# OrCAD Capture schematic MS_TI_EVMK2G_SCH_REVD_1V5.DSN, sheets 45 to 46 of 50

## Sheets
45 44. BOARD MANAGEMENT CONTROL_1: size C; title: BOARD MANAGEMENT CONTROL_1
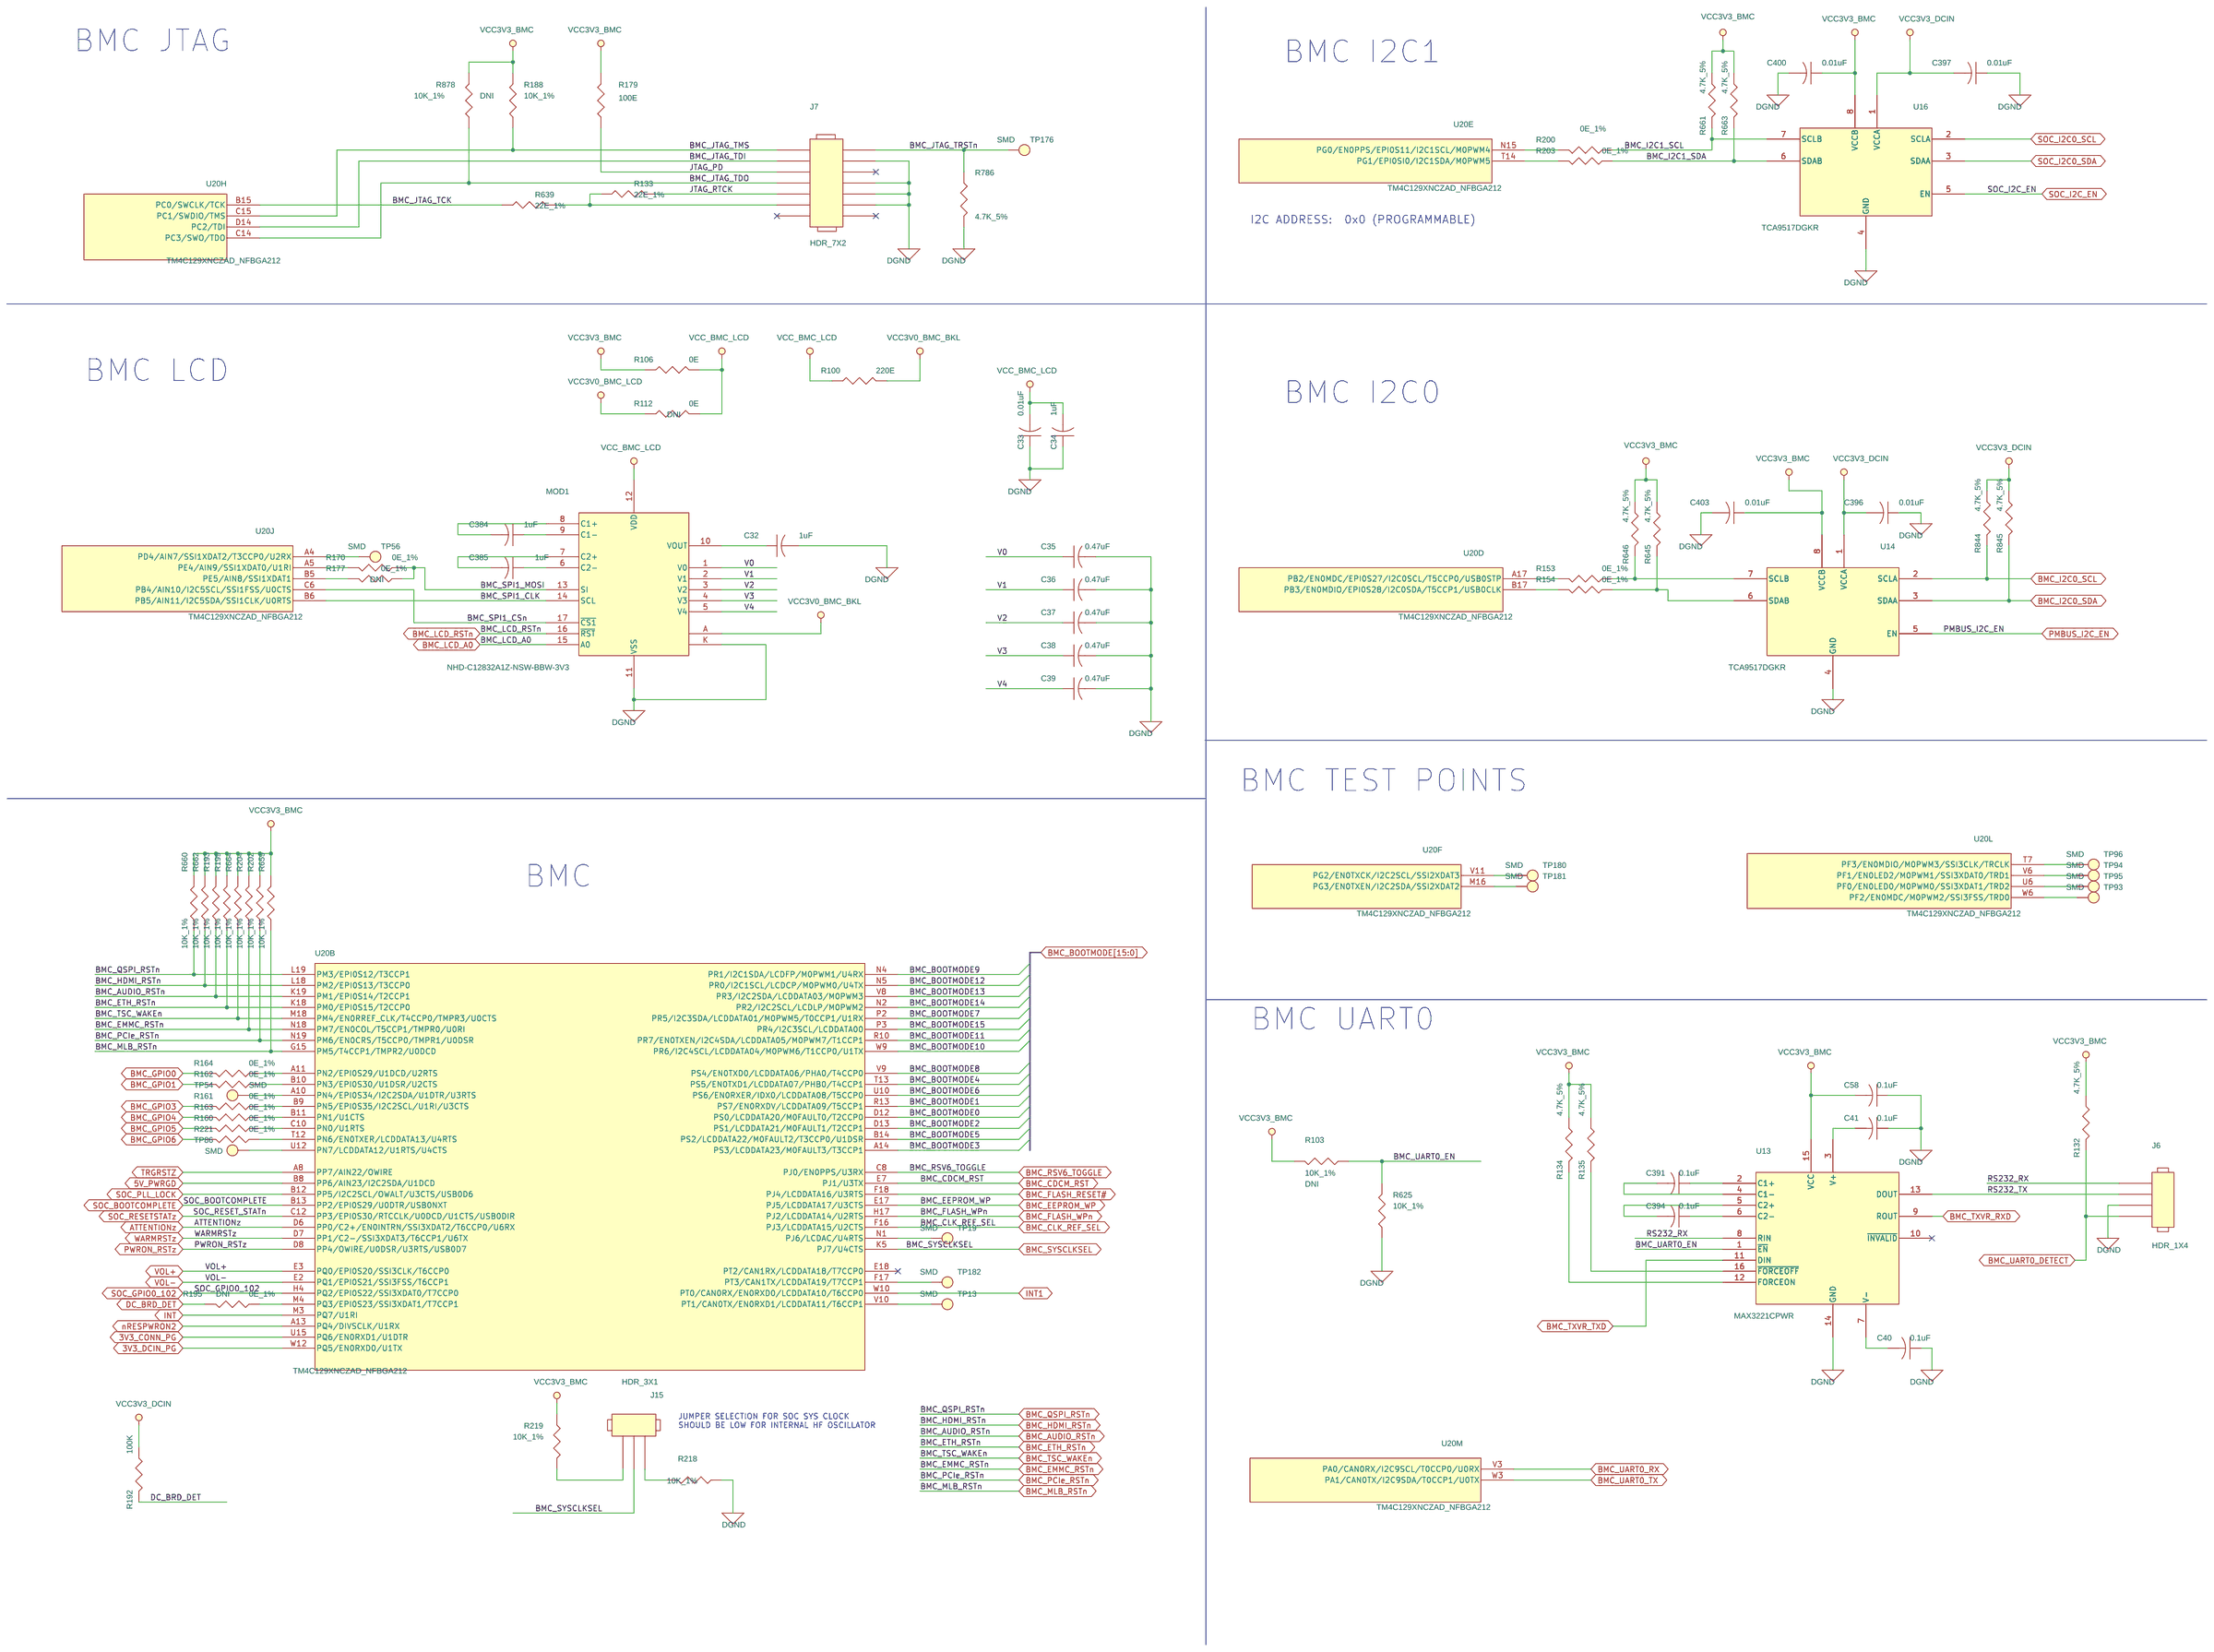
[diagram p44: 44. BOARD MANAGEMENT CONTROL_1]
46 45. BOARD MANAGEMENT CONTROL_2: size C; title: BOARD MANAGEMENT CONTROL_2
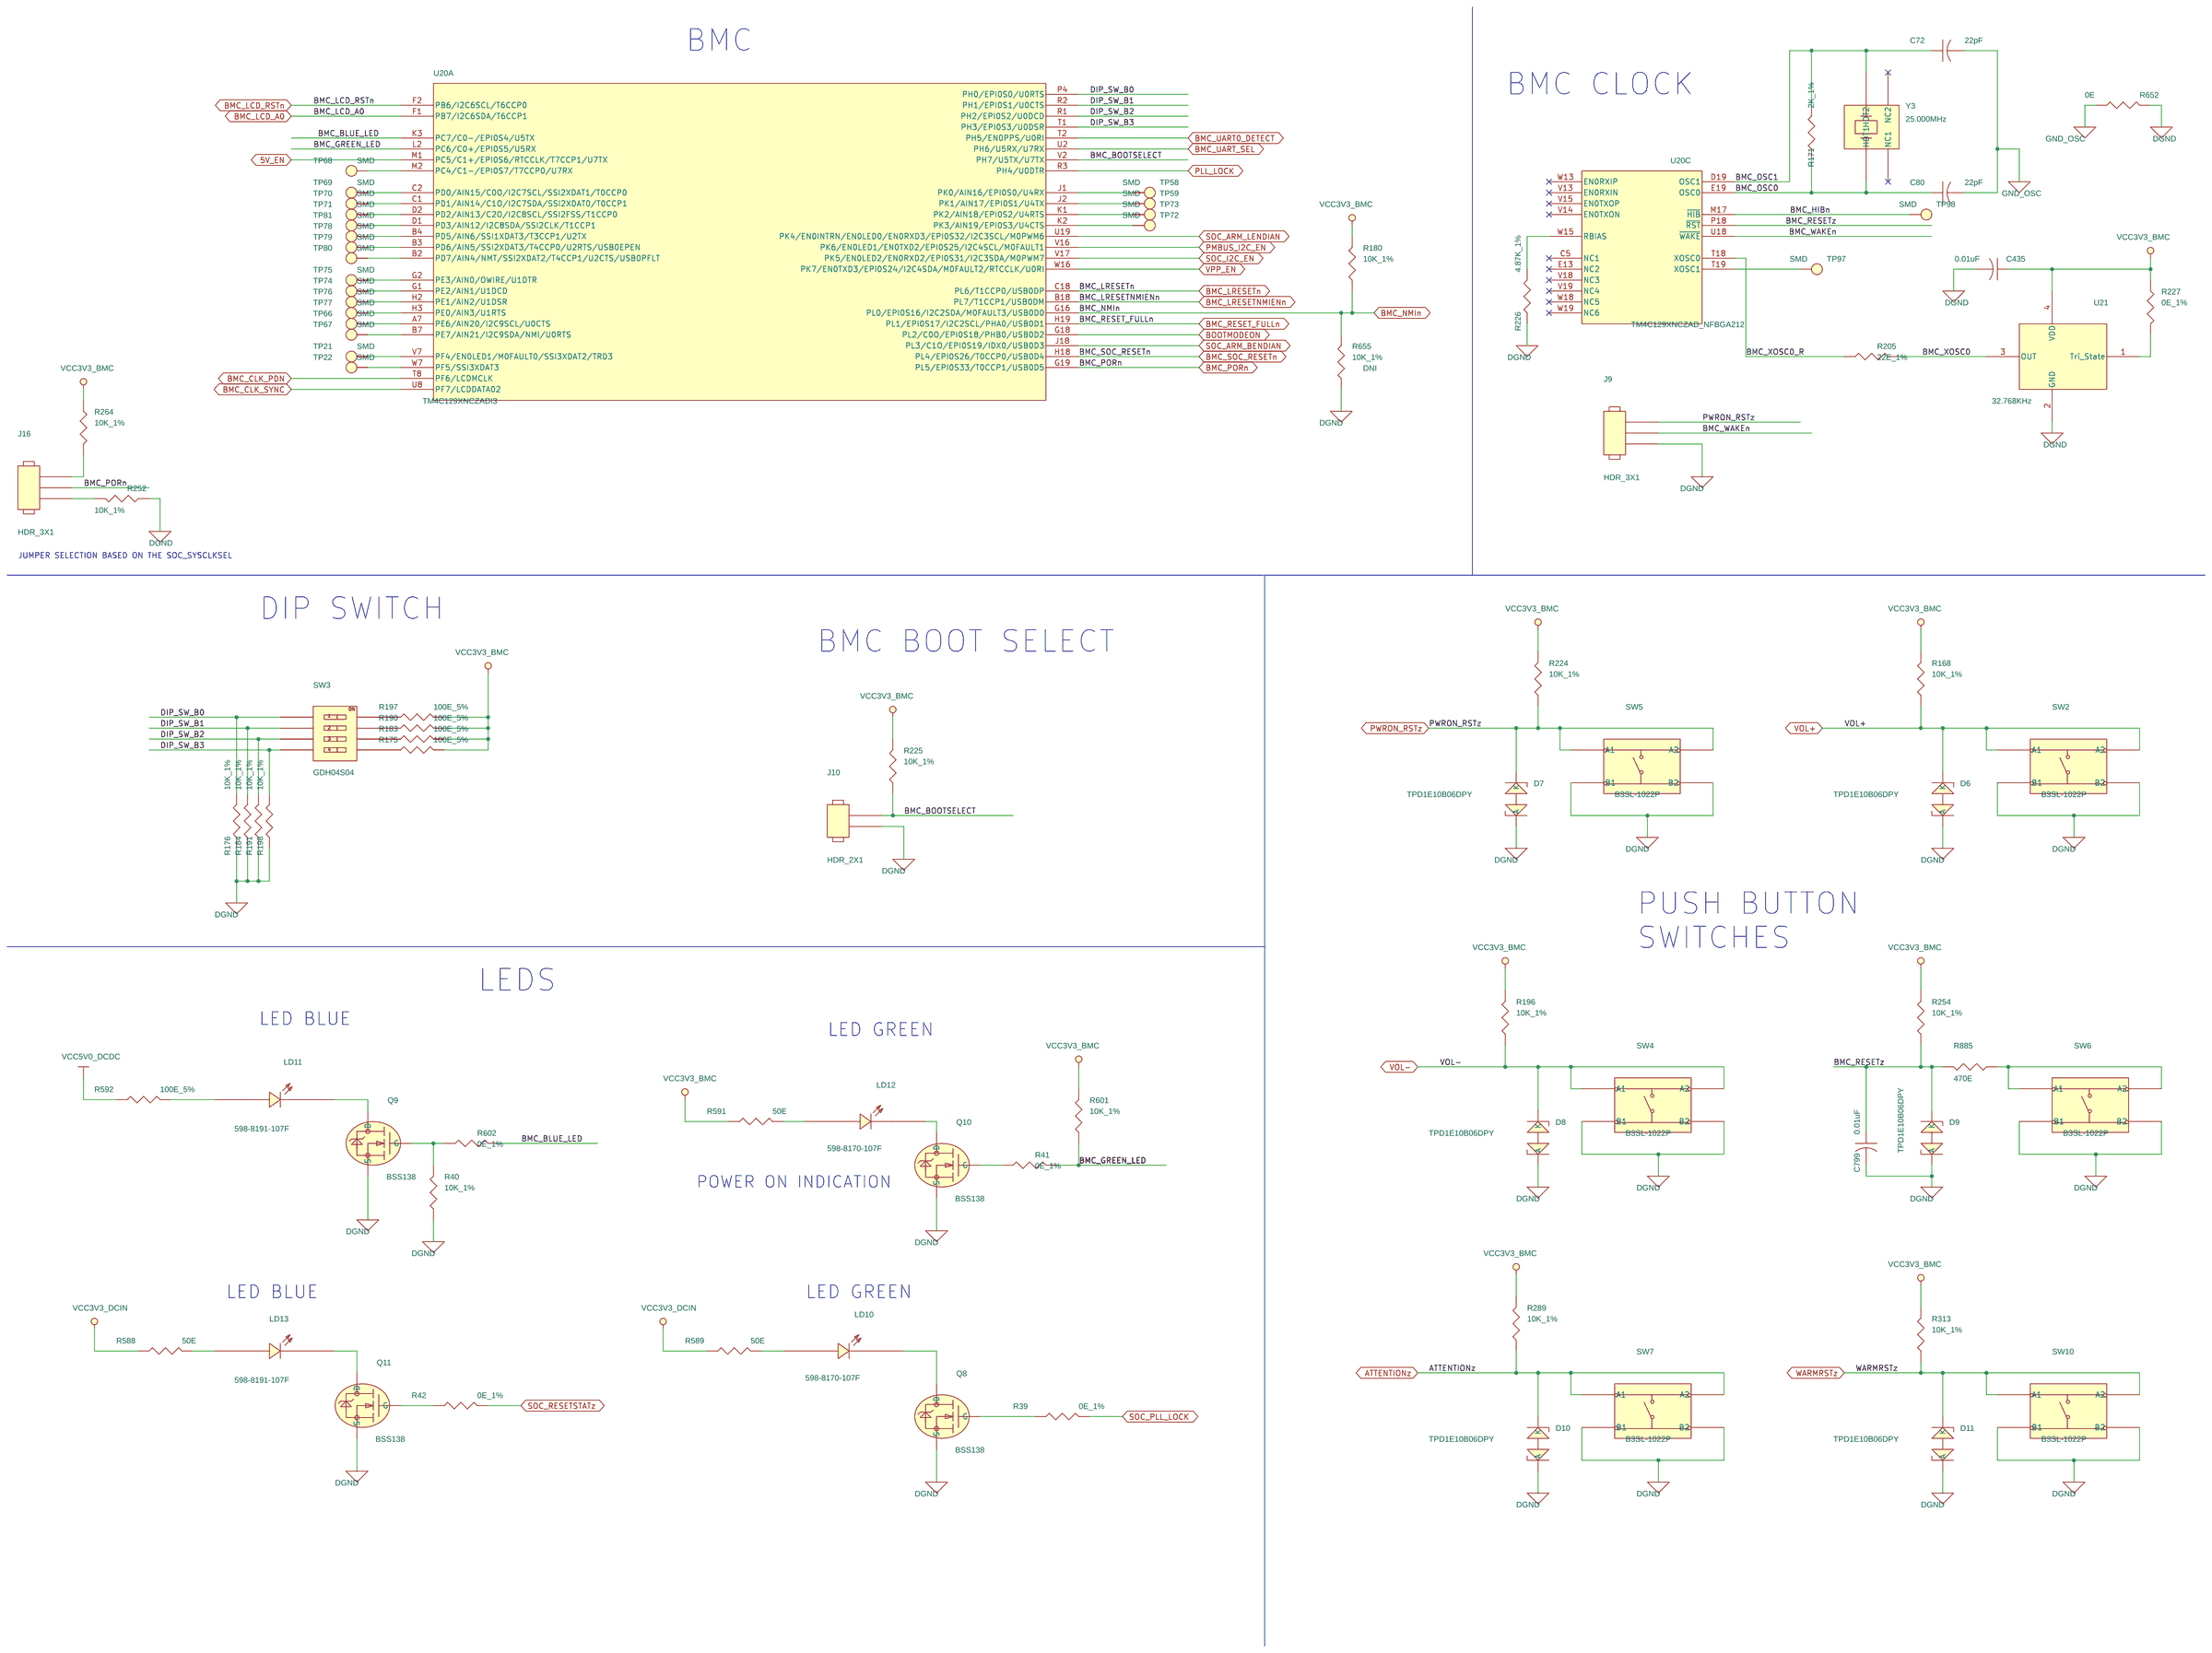
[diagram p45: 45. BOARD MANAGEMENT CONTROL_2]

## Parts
sheet 44. BOARD MANAGEMENT CONTROL_1
C32  1uF  [CAP0603]
C33  0.01uF  [CAP0402]
C34  1uF  [CAP0402]
C35  0.47uF  [CAP0603]
C36  0.47uF  [CAP0603]
C37  0.47uF  [CAP0603]
C38  0.47uF  [CAP0603]
C39  0.47uF  [CAP0603]
C40  0.1uF  [CAP0402]
C41  0.1uF  [CAP0402]
C58  0.1uF  [CAP0402]
C384  1uF  [CAP0402]
C385  1uF  [CAP0402]
C391  0.1uF  [CAP0402]
C394  0.1uF  [CAP0402]
C396  0.01uF  [CAP0402]
C397  0.01uF  [CAP0402]
C400  0.01uF  [CAP0402]
C403  0.01uF  [CAP0402]
J6  HDR_1X4  [HDR_1X4_100_640454-4_S_T]
J7  HDR_7X2  [HDR_7X2_100_S_T]
J15  HDR_3X1  [HDR_3X1_100_S_T]
MOD1  NHD-C12832A1Z-NSW-BBW-3V3  [MOD17_NHD-C12832A1Z]
R100  220E  [RES0805]
R103  10K_1%  [RES0402]
R106  0E  [RES0402]
R112  0E  [RES0402]
R132  4.7K_5%  [RES0402]
R133  22E_1%  [RES0402]
R134  4.7K_5%  [RES0402]
R135  4.7K_5%  [RES0402]
R153  0E_1%  [RES0402]
R154  0E_1%  [RES0402]
R160  0E_1%  [RES0402]
R161  0E_1%  [RES0402]
R162  0E_1%  [RES0402]
R163  0E_1%  [RES0402]
R164  0E_1%  [RES0402]
R170  0E_1%  [RES0402]
R177  0E_1%  [RES0402]
R179  100E  [RES0402]
R188  10K_1%  [RES0402]
R192  100K  [RES0402]
R193  10K_1%  [RES0402]
R195  0E_1%  [RES0402]
R199  10K_1%  [RES0402]
R200  0E_1%  [RES0402]
R202  10K_1%  [RES0402]
R203  0E_1%  [RES0402]
R204  10K_1%  [RES0402]
R218  10K_1%  [RES0402]
R219  10K_1%  [RES0402]
R221  0E_1%  [RES0402]
R625  10K_1%  [RES0402]
R639  22E_1%  [RES0402]
R645  4.7K_5%  [RES0402]
R646  4.7K_5%  [RES0402]
R659  10K_1%  [RES0402]
R660  10K_1%  [RES0402]
R661  4.7K_5%  [RES0402]
R662  10K_1%  [RES0402]
R663  4.7K_5%  [RES0402]
R664  10K_1%  [RES0402]
R786  4.7K_5%  [RES0402]
R844  4.7K_5%  [RES0402]
R845  4.7K_5%  [RES0402]
R878  10K_1%  [RES0402]
TP13  SMD  [TP40_SMD]
TP19  SMD  [TP40_SMD]
TP54  SMD  [TP40_SMD]
TP56  SMD  [TP40_SMD]
TP86  SMD  [TP40_SMD]
TP93  SMD  [TP40_SMD]
TP94  SMD  [TP40_SMD]
TP95  SMD  [TP40_SMD]
TP96  SMD  [TP40_SMD]
TP176  SMD  [TP40_SMD]
TP180  SMD  [TP40_SMD]
TP181  SMD  [TP40_SMD]
TP182  SMD  [TP40_SMD]
U13  MAX3221CPWR  [TSSOP16_25-59_205X180]
U14  TCA9517DGKR  [VSSOP8_25-59_120X120]
U16  TCA9517DGKR  [VSSOP8_25-59_120X120]
sheet 45. BOARD MANAGEMENT CONTROL_2
C72  22pF  [CAP0402]
C80  22pF  [CAP0402]
C435  0.01uF  [CAP0402]
C799  0.01uF  [CAP0402]
D6  TPD1E10B06DPY  [DIO_DFN0402]
D7  TPD1E10B06DPY  [DIO_DFN0402]
D8  TPD1E10B06DPY  [DIO_DFN0402]
D9  TPD1E10B06DPY  [DIO_DFN0402]
D10  TPD1E10B06DPY  [DIO_DFN0402]
D11  TPD1E10B06DPY  [DIO_DFN0402]
J9  HDR_3X1  [HDR_3X1_100_S_T]
J10  HDR_2X1  [HDR_2X1_100_S_T]
J16  HDR_3X1  [HDR_3X1_100_S_T]
LD10  598-8170-107F  [LED_0805]
LD11  598-8191-107F  [LED_0805]
LD12  598-8170-107F  [LED_0805]
LD13  598-8191-107F  [LED_0805]
Q8  BSS138  [TO_SOT23-123]
Q9  BSS138  [TO_SOT23-123]
Q10  BSS138  [TO_SOT23-123]
Q11  BSS138  [TO_SOT23-123]
R39  0E_1%  [RES0402]
R40  10K_1%  [RES0402]
R41  0E_1%  [RES0402]
R42  0E_1%  [RES0402]
R168  10K_1%  [RES0402]
R171  2K_1%  [RES0402]
R175  100E_5%  [RES0402]
R176  10K_1%  [RES0402]
R180  10K_1%  [RES0402]
R183  100E_5%  [RES0402]
R184  10K_1%  [RES0402]
R190  100E_5%  [RES0402]
R191  10K_1%  [RES0402]
R196  10K_1%  [RES0402]
R197  100E_5%  [RES0402]
R198  10K_1%  [RES0402]
R205  22E_1%  [RES0402]
R224  10K_1%  [RES0402]
R225  10K_1%  [RES0402]
R226  4.87K_1%  [RES0402]
R227  0E_1%  [RES0402]
R252  10K_1%  [RES0402]
R254  10K_1%  [RES0402]
R264  10K_1%  [RES0402]
R289  10K_1%  [RES0402]
R313  10K_1%  [RES0402]
R588  50E  [RES0402]
R589  50E  [RES0402]
R591  50E  [RES0402]
R592  100E_5%  [RES0402]
R601  10K_1%  [RES0402]
R602  0E_1%  [RES0402]
R652  0E  [RES0402]
R655  10K_1%  [RES0402]
R885  470E  [RES0402]
SW2  B3SL-1022P  [SW4_EVQQ2_255X240_SMD]
SW3  GDH04S04  [SW8_GDH04S04_265X245]
SW4  B3SL-1022P  [SW4_EVQQ2_255X240_SMD]
SW5  B3SL-1022P  [SW4_EVQQ2_255X240_SMD]
SW6  B3SL-1022P  [SW4_EVQQ2_255X240_SMD]
SW7  B3SL-1022P  [SW4_EVQQ2_255X240_SMD]
SW10  B3SL-1022P  [SW4_EVQQ2_255X240_SMD]
TP21  SMD  [TP40_SMD]
TP22  SMD  [TP40_SMD]
TP58  SMD  [TP40_SMD]
TP59  SMD  [TP40_SMD]
TP66  SMD  [TP40_SMD]
TP67  SMD  [TP40_SMD]
TP68  SMD  [TP40_SMD]
TP69  SMD  [TP40_SMD]
TP70  SMD  [TP40_SMD]
TP71  SMD  [TP40_SMD]
TP72  SMD  [TP40_SMD]
TP73  SMD  [TP40_SMD]
TP74  SMD  [TP40_SMD]
TP75  SMD  [TP40_SMD]
TP76  SMD  [TP40_SMD]
TP77  SMD  [TP40_SMD]
TP78  SMD  [TP40_SMD]
TP79  SMD  [TP40_SMD]
TP80  SMD  [TP40_SMD]
TP81  SMD  [TP40_SMD]
TP97  SMD  [TP40_SMD]
TP98  SMD  [TP40_SMD]
U21  32.768KHz  [OSC4_ASEK_130X110_SMD]
Y3  25.000MHz  [XTAL4_NX3225GA_130X100_SMD]
sheet 46. BOARD MANAGEMENT CONTROL_3
U20  TM4C129XNCZADI3  [NFBGA212_19-68_400X400]  (sections A,B,C,D,E,F,G,H,I,J,K,L,M,N,O)

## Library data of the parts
C32 = CAP: CAP CERAMIC 1uF 25V 10% X7R 0603; Chkd/date: BAVISH/040311; Crtd /date: MAZHAR/190111; Custom_Duty: 15%; Customs_HS_Code: 85322990; Distributor_name: DIGIKEY; Distributor_part_number: 490-5307-1-ND; Height: 0.90MM; Mfr_name: MURATA; Mfr_part_number: GRM188R71E105KA12D; Mistral Part No: 120011010017-R; Package: 0603; Part_type: CAPACITORS\CERAMIC; Project: ITS-PWR_CARD; RoHS: RoHS; Temperature: -55°C+125°C; Tolerance: 10%; Voltage: 25V; Wattage: NA; Weight: NA; Datasheet: Y:\MIS_DATABASE\DATASHEETS\CAPACITORS\GRM188SERIES.PDF
C33 C396 C397 C400 C403 C435 C799 = CAP: CAP CERAMIC 0.01uF 16V 10% X7R 0402; Alternate_mfr_name_A: AVX CORPORATION; Alternate_mfr_name_B: KEMET; Alternate_mfr_name_D: TDK CORPORATION; Alternate_mfr_part_number_A: 0402YC103KAT2A; Alternate_mfr_part_number_B: C0402C103K4RACTU; Alternate_mfr_part_number_D: C1005X7R1C103K; Chkd/date: SHREESHAIL/180506; Crtd /date: MAZHAR/110506; Custom_Duty: 15%; Customs_HS_Code: 85322990; Distributor_name: DIGIKEY; Distributor_name_A: DIGIKEY; Distributor_name_B: DIGIKEY; Distributor_name_D: DIGIKEY; Distributor_part_number: PCC103BQCT-ND; Distributor_part_number_A: 478-1114-1-ND; Distributor_part_number_B: 399-1038-1-ND; Distributor_part_number_D: 445-1262-1-ND; Height: 0.55MM; Mfr_name: PANASONIC-ECG; Mfr_part_number: ECJ-0EB1C103K; Mistral Part No: 120009030032-R; Package: 0402; Part_type: CAPACITORS\CERAMIC; Project: VOCERA; RoHS: RoHS; Tolerance: 10%; Voltage: 16V; Datasheet: Y:\MIS_DATABASE\DATASHEETS\CAPACITORS\PAN-ECJ.PDF
C34 C384 C385 = CAP: CAP CERAMIC 1uF 10V 10% X5R 0402; Chkd/date: BALACHANDAR/160514; Crtd /date: SARANYA/060514; Custom_Duty: 15%; Customs_HS_Code: 85322990; Distributor_name: DIGIKEY; Distributor_part_number: 478-4596-1-ND; Height: 0.56MM; Mfr_name: AVX CORPORATION; Mfr_part_number: 0402ZD105KAT2A; Mistral Part No: 120014050010-R; Package: 0402; Part_type: CAPACITORS\CERAMIC; Project: AEGIS GP BETA2; RoHS: RoHS; Temperature: -55°C+85°C; Tolerance: 10%; Voltage: 10V; Wattage: NA; Weight: NA; Datasheet: Y:\MIS_DATABASE\DATASHEETS\CAPACITORS\AVX_MLC.PDF
C35-C39 = CAP: CAP CERAMIC 0.47uF 25V 10% X7R 0603; Chkd/date: MAZHAR/130809; Crtd /date: USMAN/070808; Custom_Duty: 15%; Customs_HS_Code: 85322990; Distributor_name: DIGIKEY; Distributor_part_number: 490-3291-1-ND; Height: 0.90MM; Mfr_name: MURATA; Mfr_part_number: GRM188R71E474KA12D; Mistral Part No: 120009030111; Package: 0603; Part_type: CAPACITORS\CERAMIC; Project: REVA-IBMS; Tolerance: 10%; Voltage: 25V; Datasheet: Y:\MIS_DATABASE\DATASHEETS\CAPACITORS\GRM188SERIES.PDF
C40 C41 C58 C391 C394 = CAP: CAP CERAMIC 0.1uF 16V 10% X7R 0402; Alternate_mfr_name_A: KEMET; Alternate_mfr_part_number_A: C0402C104K4RACT; Chkd/date: MAZHAR/281108; Crtd /date: MAZHAR/030907; Custom_Duty: 15%; Customs_HS_Code: 85322990; Distributor_name: DIGIKEY; Distributor_name_A: DIGIKEY; Distributor_part_number: 490-3261-1-ND; Distributor_part_number_A: 399-3521-1-ND; Height: 0.55MM; Mfr_name: MURATA; Mfr_part_number: GRM155R71C104KA88D; Mistral Part No: 120009030060-R; Package: 0402; Part_type: CAPACITORS\CERAMIC; Project: SMART VIEW_IP CAMERA; Tolerance: 10%; Voltage: 16V; Datasheet: Y:\MIS_DATABASE\DATASHEETS\CAPACITORS\GRM188SERIES.PDF
J6 = HEADER_4X1: CON HDR 1X4 2.54MM PITCH ST TH; Chkd/date: NAVEED/241114; Crtd /date: VASANTHA/071114; Custom_Duty: 24%; Customs_HS_Code: 85369090; Distributor_name: DIGIKEY; Distributor_part_number: A19431-ND; Height: 10.23MM; Mfr_name: TE CONNECTIVITY; Mfr_part_number: 640454-4; Mistral Part No: 150014110002-R; Package: THRU-HOLE; Part_type: CONNECTOR\HEADER; Project: GALILEO_EVM; RoHS: RoHS; Temperature: NA; Tolerance: NA; Voltage: NA; Wattage: NA; Weight: NA; Datasheet: Y:\MIS_DATABASE\DATASHEETS\CONNECTORS\640454.PDF
J7 = HEADER_7X2: CON HDR 7X2 2.54MM PITCH ST TH; Chkd/date: USMAN/021214; Crtd /date: CHAITHANYA/251111; Custom_Duty: 24%; Customs_HS_Code: 85369090; Distributor_name: NA; Distributor_part_number: NA; Height: 10.67MM; Mfr_name: SAMTEC; Mfr_part_number: TSW-107-25-F-D; Mistral Part No: 150011110024-R; Package: THRU-HOLE; Part_type: CONNECTOR\HEADERS; Project: NA10NG; RoHS: RoHS; Temperature: -55°C+125°C; Tolerance: NA; Voltage: NA; Wattage: NA; Weight: NA; Datasheet: Y:\MIS_DATABASE\DATASHEETS\CONNECTORS\X-TSW-SERIES.PDF
J9 J15 J16 = HEADER_3X1: CON HDR 3X1 2.54MM PITCH ST TH; Chkd/date: MAZHAR/100311; Crtd /date: BAVISH/160211; Custom_Duty: 24%; Customs_HS_Code: 85369090; Distributor_name: DIGIKEY; Distributor_part_number: A26545-ND; Height: 10.74MM; Mfr_name: TYCO ELECTRONICS; Mfr_part_number: 87224-3; Mistral Part No: 150011020004-R; Package: THRU-HOLE; Part_type: CONNECTOR\HEADERS; Project: OMAPL1_PEC20; RoHS: RoHS; Temperature: NA; Tolerance: NA; Voltage: NA; Wattage: NA; Weight: NA; Datasheet: Y:\MIS_DATABASE\DATASHEETS\CONNECTORS\87224.PDF
MOD1 = MODULE_NHD-C12832A1Z: MODULE LCD COG CHAR 128x32 WHITE BACKLIGHT WITH TRANSFLECTIVE TH; Chkd/date: NAVEED/230215; Crtd /date: NAVEED/281014; Distributor_name: DIGIKEY; Distributor_part_number: NHD-C12832A1Z-NSW-BBW-3V3-ND; Height: 5.20MM; Mfr_name: NEWHAVEN; Mistral Part No: 180014100012-R; Package: THRU-HOLE; Part_type: MISC\MODULE; Project: GALILEO_EVM; RoHS: RoHS; Temperature: -20°C+70°C; Tolerance: NA; Voltage: NA; Wattage: NA; Weight: NA; Datasheet: Y:\MIS_DATABASE\DATASHEETS\MISC\MODULES\NHD-C12832A1Z_NSW.PDF
R100 = RESISTOR: RES 220E  1/8W 5% 0805; Chkd/date: SUHAS/240910; Crtd /date: MUDDU/180210; Custom_Duty: 15%; Customs_HS_Code: 85332119; Distributor_name: DIGIKEY; Distributor_part_number: 541-220ACT-ND; Height: 0.50MM; Mfr_name: VISHAY; Mfr_part_number: CRCW0805220RJNEA; Mistral Part No: 110010020033-P; Package: 0805; Part_type: RESISTORS\FIXED; Project: NPOL_ADC; RoHS: Pb-Free; Temperature: -55°C+155°C; Tolerance: 5%; Voltage: 150V; Wattage: 1/80W; Weight: 5.5g/1000pcs; Datasheet: Y:\MIS_DATABASE\DATASHEETS\RESISTORS\CRCW.PDF
R103 R655 R878 = RESISTOR: RES 10K 1/16W 1% 0402; Alternate_mfr_name_A: AVX CORPORATION; Alternate_mfr_name_B: PANASONIC-ECG-ECG; Alternate_mfr_name_C: YAGEO AMERICA; Alternate_mfr_name_D: VISHAY; Alternate_mfr_part_number_A: CR05-103F-H; Alternate_mfr_part_number_B: ERJ-2RKF1002X; Alternate_mfr_part_number_C: 9C04021A1002FLHF3; Alternate_mfr_part_number_D: CRCW040210K0FKED; Chkd/date: SHREESHAIL/310506; Crtd /date: GEETHA/290506; Custom_Duty: 15%; Customs_HS_Code: 85332119; Distributor_name: DIGIKEY; Distributor_name_A: NA; Distributor_name_B: DIGIKEY; Distributor_name_C: DIGIKEY; Distributor_name_D: DIGIKEY; Distributor_part_number: 311-10.0KLRTR-ND; Distributor_part_number_A: NA; Distributor_part_number_B: P10.0KLCT-ND; Distributor_part_number_C: 311-10.0KLCT-ND; Distributor_part_number_D: 541-10.0KLCT-ND; Height: 0.40MM; Loading: DNI; Mfr_name: YAGEO AMERICA; Mfr_part_number: RC0402FR-0710KL; Mistral Part No: 110009030220-P; Package: 0402; Part_type: RESISTORS\FIXED; Project: VOCERA; RoHS: Pb-Free; Tolerance: 1%; Wattage: 1/16W; Datasheet: Y:\MIS_DATABASE\DATASHEETS\RESISTORS\YAGEO-RC0402.PDF
R106 R652 = RESISTOR: RES 0E 1/10W 5% 0402; Chkd/date: NAVEED/241114; Crtd /date: NAVEED/201014; Custom_Duty: 15%; Customs_HS_Code: 85332119; Distributor_name: DIGIKEY; Distributor_part_number: P0.0JCT-ND; Height: 0.40MM; Mfr_name: PANASONIC-ECG; Mfr_part_number: ERJ-2GE0R00X; Mistral Part No: 110014100008-R; Package: 0402; Part_type: RESISTORS\FIXED; Project: AEGIS POM; RoHS: RoHS; Tolerance: 5%; Wattage: 1/10W; Datasheet: Y:\MIS_DATABASE\DATASHEETS\RESISTORS\ERJ12.PDF
R112 = RESISTOR: RES 0E 1/10W 5% 0402; Chkd/date: NAVEED/241114; Crtd /date: NAVEED/201014; Custom_Duty: 15%; Customs_HS_Code: 85332119; Distributor_name: DIGIKEY; Distributor_part_number: P0.0JCT-ND; Height: 0.40MM; Loading: DNI; Mfr_name: PANASONIC-ECG; Mfr_part_number: ERJ-2GE0R00X; Mistral Part No: 110014100008-R; Package: 0402; Part_type: RESISTORS\FIXED; Project: AEGIS POM; RoHS: RoHS; Tolerance: 5%; Wattage: 1/10W; Datasheet: Y:\MIS_DATABASE\DATASHEETS\RESISTORS\ERJ12.PDF
R132 R134 R135 R645 R646 R661 R663 R786 R844 R845 = RESISTOR: RES 4.7K 1/16W 5% 0402; Chkd/date: VASANTHA/190614; Crtd /date: NAVEED/160614; Custom_Duty: 15%; Customs_HS_Code: 85332119; Distributor_name: DIGIKEY; Distributor_part_number: RMCF0402JT4K70CT-ND; Height: 0.40MM; Mfr_name: STACKPOLE ELECTRONICS; Mfr_part_number: RMCF0402JT4K70; Mistral Part No: 110014060028-R; Package: 0402; Part_type: RESISTORS\FIXED; Project: AEGIS_POM; RoHS: RoHS; Temperature: -55°C+155°C; Tolerance: 5%; Voltage: NA; Wattage: 1/16W; Weight: NA; Datasheet: Y:\MIS_DATABASE\DATASHEETS\RESISTORS\RMCF-SERIES1.PDF
R133 R205 R639 = RESISTOR: RES 22E 1/16W 1% 0402; Alternate_mfr_name_A: VISHAY; Alternate_mfr_part_number_A: CRCW040222R0FKED; Chkd/date: SUHAS/290910; Crtd /date: MAZHAR/090909; Custom_Duty: 15%; Customs_HS_Code: 85332119; Distributor_name: DIGIKEY; Distributor_name_A: DIGIKEY; Distributor_part_number: 311-22.0LRCT-ND; Distributor_part_number_A: 541-22.0LCT-ND; Height: 0.40MM; Mfr_name: YAGEO AMERICA; Mfr_part_number: RC0402FR-0722RL; Mistral Part No: 110009090004-P; Package: 0402; Part_type: RESISTORS\FIXED; Project: VMEFMCD; Remarks: In alternate datasheet it is RoHS COMPLIANT. Y:\MIS_DATABASE\DATASHEETS\RESISTORS\CRCW0402.PDF; RoHS: Pb-Free; Temperature: -55°C+155°C; Tolerance: 1%; Voltage: 50V; Wattage: 1/16W; Weight: 0.8g/1000pcs; Datasheet: Y:\MIS_DATABASE\DATASHEETS\RESISTORS\YAGEO-RC0402.PDF
R39 R41 R42 R153 R154 R160-R164 R170 R200 R203 R221 R227 R602 = RESISTOR: RES 0E 1/16W 1% 0402; Chkd/date: MAZHAR/220709; Crtd /date: USMAN/270109; Custom_Duty: 15%; Customs_HS_Code: 85332119; Distributor_name: NA; Distributor_part_number: NA; Height: 0.40MM; Mfr_name: YAGEO AMERICA; Mfr_part_number: RC0402FR-070RL; Mistral Part No: 110009030085-P; Package: 0402; Part_type: RESISTORS\FIXED; Project: OMAP_EVM; RoHS: Pb-Free; Tolerance: 1%; Wattage: 1/16W; Datasheet: Y:\MIS_DATABASE\DATASHEETS\RESISTORS\CRCW0603.PDF
R177 R195 = RESISTOR: RES 0E 1/16W 1% 0402; Chkd/date: MAZHAR/220709; Crtd /date: USMAN/270109; Custom_Duty: 15%; Customs_HS_Code: 85332119; Distributor_name: NA; Distributor_part_number: NA; Height: 0.40MM; Loading: DNI; Mfr_name: YAGEO AMERICA; Mfr_part_number: RC0402FR-070RL; Mistral Part No: 110009030085-P; Package: 0402; Part_type: RESISTORS\FIXED; Project: OMAP_EVM; RoHS: Pb-Free; Tolerance: 1%; Wattage: 1/16W; Datasheet: Y:\MIS_DATABASE\DATASHEETS\RESISTORS\CRCW0603.PDF
R179 = RESISTOR: RES 100E 1/16W 5% 0402; Alternate_mfr_name_A: AVX CORPORATION; Alternate_mfr_name_C: YAGEO AMERICA; Alternate_mfr_name_D: YAGEO AMERICA; Alternate_mfr_part_number_A: CR05-101J-H; Alternate_mfr_part_number_C: 9C04021A1000JLHF3; Alternate_mfr_part_number_D: RC0402JR-07100RL; Chkd/date: SHREESHAIL/210406; Crtd /date: GEETHA/200406; Custom_Duty: 15%; Customs_HS_Code: 85332119; Distributor_name: DIGIKEY; Distributor_name_A: NA; Distributor_name_C: DIGIKEY; Distributor_name_D: DIGIKEY; Distributor_part_number: P100JCT-ND; Distributor_part_number_A: NA; Distributor_part_number_C: 311-100JCT-ND; Distributor_part_number_D: 311-100JRCT-ND; Height: 0.40MM; Mfr_name: PANASONIC-ECG; Mfr_part_number: ERJ-2GEJ101X; Mistral Part No: 110009030164-R; Package: 0402; Part_type: RESISTORS\FIXED; Project: RED EYE; RoHS: RoHS; Tolerance: 5%; Wattage: 1/16W; Datasheet: Y:\MIS_DATABASE\DATASHEETS\RESISTORS\ERJ12.PDF
R40 R168 R176 R180 R184 R188 R191 R193 R196 R198 R199 R202 R204 R218 R219 R224 R225 R252 R254 R264 R289 R313 R601 R625 R659 R660 R662 R664 = RESISTOR: RES 10K 1/16W 1% 0402; Alternate_mfr_name_A: AVX CORPORATION; Alternate_mfr_name_B: PANASONIC-ECG-ECG; Alternate_mfr_name_C: YAGEO AMERICA; Alternate_mfr_name_D: VISHAY; Alternate_mfr_part_number_A: CR05-103F-H; Alternate_mfr_part_number_B: ERJ-2RKF1002X; Alternate_mfr_part_number_C: 9C04021A1002FLHF3; Alternate_mfr_part_number_D: CRCW040210K0FKED; Chkd/date: SHREESHAIL/310506; Crtd /date: GEETHA/290506; Custom_Duty: 15%; Customs_HS_Code: 85332119; Distributor_name: DIGIKEY; Distributor_name_A: NA; Distributor_name_B: DIGIKEY; Distributor_name_C: DIGIKEY; Distributor_name_D: DIGIKEY; Distributor_part_number: 311-10.0KLRTR-ND; Distributor_part_number_A: NA; Distributor_part_number_B: P10.0KLCT-ND; Distributor_part_number_C: 311-10.0KLCT-ND; Distributor_part_number_D: 541-10.0KLCT-ND; Height: 0.40MM; Mfr_name: YAGEO AMERICA; Mfr_part_number: RC0402FR-0710KL; Mistral Part No: 110009030220-P; Package: 0402; Part_type: RESISTORS\FIXED; Project: VOCERA; RoHS: Pb-Free; Tolerance: 1%; Wattage: 1/16W; Datasheet: Y:\MIS_DATABASE\DATASHEETS\RESISTORS\YAGEO-RC0402.PDF
R192 = RESISTOR: RES 100K 1/16W 5% 0402; Chkd/date: JAGADEESWARAN.S/250414; Crtd /date: BAVISH/010611; Custom_Duty: 15%; Customs_HS_Code: 85332119; Distributor_name: DIGIKEY; Distributor_part_number: 541-100KJCT-ND; Height: 0.40MM; Mfr_name: VISHAY; Mfr_part_number: CRCW0402100KJNED; Mistral Part No: 110011060002-R; Package: 0402; Part_type: RESISTORS\FIXED; Project: AM4515_EVM_LCD; RoHS: RoHS; Temperature: -55°C+155°C; Tolerance: 5%; Voltage: NA; Wattage: 1/16W; Weight: 0.65mg; Datasheet: Y:\MIS_DATABASE\DATASHEETS\RESISTORS\CRCW0603.PDF
TP13 TP19 TP21 TP22 TP54 TP56 TP58 TP59 TP66-TP81 TP86 TP93-TP98 TP176 TP180-TP182 = TESTPOINT: TESTPOINT 40 SMD; Chkd/date: MAZHAR/190505; Crtd /date: MAZHAR/190505; Distributor_name: NA; Distributor_part_number: NA; Height: NA; Mfr_name: LOCAL; Mistral Part No: 130009030933; Part_type: MISC\TESTPOINT; Project: RAINIER-3
U13 = MAX3221CPWR_TSSOP16: IC LINE DRIVER/RECEIVER SINGLECHANNEL RS-232 TSSOP16; Chkd/date: RAGESH/111110; Crtd /date: MUDDU/270510; Custom_Duty: 15%; Customs_HS_Code: 85423100; Distributor_name: DIGIKEY; Distributor_part_number: 296-9594-1-ND; Height: 1.20MM; Mfr_name: TEXAS INSTRUMENTS; Mistral Part No: 141010050010-R; Package: TSSOP16; Part_type: ICS\INTERFACE\LINE DRIVER; Project: CENTAURUS; RoHS: RoHS; Temperature: 0°C to 70°C; Datasheet: Y:\MIS_DATABASE\DATASHEETS\ICS\INTERFACE\MAX3221.PDF
U14 U16 = TCA9517DGKR_VSSOP8: IC 2-CHANNEL I2C BUS REPEATER VSSOP8; Chkd/date: USMAN/161213; Crtd /date: USMAN/161213; Custom_Duty: 15%; Customs_HS_Code: 85423100; Distributor_name: DIGIKEY; Distributor_part_number: 296-35972-1-ND; Height: 1.10MM; Mfr_name: TEXAS INSTRUMENTS; Mistral Part No: 141013120007-R; Package: VSSOP8; Part_type: ICS\DIGITAL\BUSTRANSCEIVER; Project: DMP; RoHS: RoHS; Temperature: -40°C+85°C; Tolerance: NA; Voltage: NA; Wattage: NA; Weight: NA; Datasheet: Y:\MIS_DATABASE\DATASHEETS\ICS\DIGITAL\BUSTRANSCEIVER\TCA9517D.PDF
C72 C80 = CAP: CAP CERAMIC 22pF 25V 5% NP0 0402; Chkd/date: SHREESHAIL/291105; Crtd /date: MAZHAR/040505; Custom_Duty: 15%; Customs_HS_Code: 85322990; Distributor_name: DIGIKEY; Distributor_part_number: 04023A220JAT2A-ND; Height: 0.60MM; Mfr_name: AVX CORPORATION; Mfr_part_number: 04023A220JAT2A; Mistral Part No: 120009030322-R; Package: 0402; Part_type: CAPACITORS\CERAMIC; Project: TELEMATICS-02; RoHS: RoHS; Tolerance: 5%; Voltage: 25V; Datasheet: Y:\MIS_DATABASE\DATASHEETS\CAPACITORS\AVX_MLC.PDF
D6-D11 = DIODE_PESD: DIODE 1CH ESD PROTECTION SMD(0402); Chkd/date: USMAN/021214; Crtd /date: VASANTHA/181114; Custom_Duty: 15%; Customs_HS_Code: 85423100; Distributor_name: DIGIKEY; Distributor_part_number: 296-30406-1-ND; Height: 0.45MM; Mfr_name: TEXAS INSTRUMENTS; Mistral Part No: 130014110022-R; Package: SMD; Part_type: DIODE\MISC; Project: GALILEO_EVM; RoHS: RoHS; Temperature: -40°C+125°C; Tolerance: NA; Voltage: NA; Wattage: NA; Weight: NA; Datasheet: Y:\MIS_DATABASE\DATASHEETS\ICS\INTERFACE\TPD1E10B06.PDF
J10 = HEADER_2X1: CON HDR 2X1 2.54MM PITCH ST TH; Alternate_mfr_name_A: SULLINS ELECTRONICS; Alternate_mfr_name_B: SAMTEC; Alternate_mfr_name_C: HANTRONIX; Alternate_mfr_part_number_A: PZC02SAAN; Alternate_mfr_part_number_B: TLW-102-06-G-S; Alternate_mfr_part_number_C: HDM20216L; Chkd/date: SHREESHAIL/140206; Crtd /date: MAZHAR/280405; Custom_Duty: 24%; Customs_HS_Code: 85369090; Distributor_name: DIGIKEY; Distributor_part_number: WM4000-ND; Height: 10.79MM; Mfr_name: MOLEX; Mfr_part_number: 22-03-2021; Mistral Part No: 150009030246-R; Package: THRU-HOLE; Part_type: CONNECTOR\HEADERS; Project: FPGA EXTENDER CARD; RoHS: RoHS; Datasheet: Y:\MIS_DATABASE\DATASHEETS\CONNECTORS\HEADER_X4030.PDF
LD10 LD12 = LED_598-8170-107F: LED ALINGAP GREEN CLEAR 0805 SMD; Chkd/date: BALACHANDAR/160514; Crtd /date: SARANYA/070514; Custom_Duty: 24%; Customs_HS_Code: 85437099; Distributor_name: DIGIKEY; Distributor_part_number: 350-2044-1-ND; Height: 0.70MM; Mfr_name: DIALIGHT; Mistral Part No: 130014050065-R; Package: 0805; Part_type: OPTO\LED; Project: AEGIS GP BETA2; RoHS: RoHS; Temperature: NA; Tolerance: NA; Voltage: NA; Wattage: NA; Weight: NA; Datasheet: Y:\MIS_DATABASE\DATASHEETS\DISCRETES\LEDS\598-SER.PDF
LD11 LD13 = LED_598-8170-107F: LED ALINGAP BLUE CLEAR 0805 SMD; Chkd/date: BALACHANDAR/160514; Crtd /date: SARANYA/070514; Custom_Duty: 24%; Customs_HS_Code: 85437099; Distributor_name: DIGIKEY; Distributor_part_number: 350-2046-1-ND; Height: 0.70MM; Mfr_name: DIALIGHT; Mistral Part No: 130014050068-R; Package: 0805; Part_type: OPTO\LED; Project: AEGIS GP BETA2; RoHS: RoHS; Temperature: NA; Tolerance: NA; Voltage: NA; Wattage: NA; Weight: NA; Datasheet: Y:\MIS_DATABASE\DATASHEETS\DISCRETES\LEDS\598-SER.PDF
Q8-Q11 = MOSFET_BSS138: IC MOSFET N-CHANNEL 50V 200mA SOT23-3; Chkd/date: SUHAS/191010; Crtd /date: USMAN/240709; Custom_Duty: 15%; Customs_HS_Code: 85423100; Distributor_name: DIGIKEY; Distributor_part_number: BSS138CT-ND; Height: 1.20MM; Mfr_name: DIODES INC; Mfr_part_number: BSS138-7-F; Mistral Part No: 142009070019-R; Package: SOT23-3; Part_type: ICS\POWER\MOSFET; Project: KHAN_MAIN; RoHS: RoHS; Temperature: -55°C+150°C; Voltage: 50V; Wattage: 300mW; Weight: 0.008g; Datasheet: Y:\MIS_DATABASE\DATASHEETS\DISCRETES\TRANSISTORS_FETS\BSS138.PDF
R171 = RESISTOR: RES 2K 1/16W 1% 0402; Alternate_mfr_name_A: YAGEO AMERICA; Alternate_mfr_name_B: PANASONIC-ECG; Alternate_mfr_name_D: VENKEL; Alternate_mfr_part_number_A: RC0402FR-072KL; Alternate_mfr_part_number_B: ERJ-S02F2001X; Alternate_mfr_part_number_D: CR0402-16W-2001FT; Chkd/date: SHREESHAIL/210506; Crtd /date: MAZHAR/150506; Custom_Duty: 15%; Customs_HS_Code: 85332119; Distributor_name: DIGIKEY; Distributor_name_A: DIGIKEY; Distributor_name_B: DIGIKEY; Distributor_name_D: NA; Distributor_part_number: P2.00KLCT-ND; Distributor_part_number_A: 311-2KLRCT-ND; Distributor_part_number_B: ERJ-S02F2001X-ND; Distributor_part_number_D: NA; Height: 0.40MM; Mfr_name: PANASONIC-ECG; Mfr_part_number: ERJ-2RKF2001X; Mistral Part No: 110009030606-R; Package: 0402; Part_type: RESISTORS\FIXED; Project: VOCERA; RoHS: RoHS; Tolerance: 1%; Wattage: 1/16W; Datasheet: Y:\MIS_DATABASE\DATASHEETS\RESISTORS\ERJ-2R.PDF
R175 R183 R190 R197 R592 = RESISTOR: RES 100E 1/16W 5% 0402; Chkd/date: VASANTHA/200614; Crtd /date: NAVEED/170614; Custom_Duty: 15%; Customs_HS_Code: 85332119; Distributor_name: DIGIKEY; Distributor_part_number: RMCF0402JT100RCT-ND; Height: 0.40MM; Mfr_name: STACKPOLE ELECTRONICS; Mfr_part_number: RMCF0402JT100R; Mistral Part No: 110014060039-R; Package: 0402; Part_type: RESISTORS\FIXED; Project: AEGIS_POM; RoHS: RoHS; Temperature: -55°C+155°C; Tolerance: 5%; Voltage: NA; Wattage: 1/16W; Weight: NA; Datasheet: Y:\MIS_DATABASE\DATASHEETS\RESISTORS\RMCF-SERIES1.PDF
R226 = RESISTOR: RES 4.87K 1/16W 1% 0402; Chkd/date: MAZHAR/150709; Crtd /date: USMAN/150109; Custom_Duty: 15%; Customs_HS_Code: 85332119; Distributor_name: DIGIKEY; Distributor_part_number: P4.87KLCT-ND; Height: 0.40MM; Mfr_name: PANASONIC-ECG; Mfr_part_number: ERJ2RKF4871X; Mistral Part No: 110009030803-R; Package: 0402; Part_type: RESISTORS\FIXED; Project: BSN-II; RoHS: RoHS; Tolerance: 1%; Wattage: 1/16W; Datasheet: Y:\MIS_DATABASE\DATASHEETS\RESISTORS\PAN-ERJSERIES.PDF
R588 R589 R591 = RESISTOR: RES 50E 1/16W 5% 0402; Chkd/date: USMAN/030114; Crtd /date: USMAN/151013; Custom_Duty: 15%; Customs_HS_Code: 85332119; Distributor_name: MOUSER; Distributor_part_number: 603-AC0402JR-0750RL; Height: 0.37MM; Mfr_name: YAGEO; Mfr_part_number: AC0402JR-0750RL; Mistral Part No: 110013100004-R; Package: 0402; Part_type: RESISTORS\FIXED; Project: C-BAND_SYNTH; RoHS: RoHS; Temperature: -55°C+155°C; Tolerance: 5%; Voltage: NA; Wattage: 1/16W; Weight: NA; Datasheet: Y:\MIS_DATABASE\DATASHEETS\RESISTORS\AC_SERIES.PDF
R885 = RESISTOR: RES 470E 1/16W 5% 0402; Alternate_mfr_name_A: AVX CORPORATION; Alternate_mfr_name_C: YAGEO AMERICA; Alternate_mfr_part_number_A: CR05-471J-H; Alternate_mfr_part_number_C: 9C04021A4700JLHF3; Chkd/date: SHREESHAIL/24050; Crtd /date: MAZHAR/260706; Custom_Duty: 15%; Customs_HS_Code: 85332119; Distributor_name: DIGIKEY; Distributor_name_A: NA; Distributor_name_C: DIGIKEY; Distributor_part_number: P470JCT-ND; Distributor_part_number_A: NA; Distributor_part_number_C: 311-470JCT-ND; Height: 0.40MM; Mfr_name: PANASONIC-ECG; Mfr_part_number: ERJ-2GEJ471X; Mistral Part No: 110009030859-R; Package: 0402; Part_type: RESISTORS\FIXED; Project: POWERBOX; RoHS: RoHS; Tolerance: 5%; Wattage: 1/16W; Datasheet: Y:\MIS_DATABASE\DATASHEETS\RESISTORS\ERJ12.PDF
SW2 SW4-SW7 SW10 = SWTACT_1_EVQQ2: TACTILE SWITCH SPST-NO SMD; Chkd/date: VASANTHA/140714; Crtd /date: NAVEED/170614; Custom_Duty: 24%; Customs_HS_Code: 85369090; Distributor_name: DIGIKEY; Distributor_part_number: SW1065CT-ND; Height: 5.10MM; Mfr_name: OMRON; Mistral Part No: 130014060032-R; Package: SMD; Part_type: ELECTRO-MECHANICAL\SWITCH; Project: AEGIS_POM; RoHS: RoHS; Temperature: -25°C+90°C; Tolerance: NA; Voltage: NA; Wattage: NA; Weight: NA; Datasheet: Y:\MIS_DATABASE\DATASHEETS\MISC\SWITCHES\B3SL.PDF
SW3 = SW8_GDH04S04: SWITCH DIP SLIDE SMD; Chkd/date: BAVISH/101111; Crtd /date: CHAITHANYA\041111; Custom_Duty: 24%; Customs_HS_Code: 85369090; Distributor_name: DIGIKEY; Distributor_part_number: 450-1353-ND; Height: 2.31MM; Mfr_name: TE CONNECTIVITY; Mistral Part No: 130011110008-R; Package: SMD; Part_type: ELECTRO-MECHANICAL\SWITCH; Project: NA10NG; RoHS: RoHS; Temperature: -30°C+85°C; Tolerance: NA; Voltage: NA; Wattage: NA; Weight: NA; Datasheet: Y:\MIS_DATABASE\DATASHEETS\MISC\SWITCHES\GDH-SERIES.PDF
U21 = OSC_TGOV: OSC 32.768KHz 3.3V SMD; Chkd/date: MAZHAR/230311; Crtd /date: BAVISH/150311; Custom_Duty: 24%; Customs_HS_Code: 85437099; Distributor_name: DIGIKEY; Distributor_part_number: 535-9998-1-ND; Height: 1.20MM; Mfr_name: ABRACON; Mfr_part_number: ASEK-32.768KHZ-LRT; Mistral Part No: 130011030004-R; Package: SMD; Part_type: OSCILLATORS; Project: PB BUG BASE; RoHS: RoHS; Temperature: -40°C+85°C; Tolerance: NA; Voltage: NA; Wattage: NA; Weight: NA; Datasheet: Y:\MIS_DATABASE\DATASHEETS\MISC\CRY_OSC\ASEK.PDF
Y3 = CRY_CX3225GB: CRY 25.000MHZ 8PF SMD; Chkd/date: NAVEED/070115; Crtd /date: VASANTHA/111114; Custom_Duty: 24%; Customs_HS_Code: 85439000; Distributor_name: DIGIKEY; Distributor_part_number: 1253-1353-1-ND; Height: 0.90MM; Mfr_name: KYOCERA; Mfr_part_number: CX3225SB25000D0FFFCC; Mistral Part No: 130014110014-R; Package: SMD; Part_type: CRYSTAL; Project: GALILEO_EVM; RoHS: RoHS; Temperature: -40°C+85°C; Tolerance: NA; Voltage: NA; Wattage: NA; Weight: NA; Datasheet: Y:\MIS_DATABASE\DATASHEETS\MISC\CRY_OSC\CX3225SB.PDF
U20 = TM4C129XNCZAD_NFBGA212: IC TIVA C SERIES MICROCONTROLLER NFBGA212; Chkd/date: NAVEED/060115; Color: Default; Crtd /date: VASANTHA/240914; Custom_Duty: 15%; Customs_HS_Code: 85423100; Distributor_name: DIGIKEY; Distributor_part_number: 296-37958-ND; Height: 1.00MM; Location X-Coordinate: 0; Location Y-Coordinate: 0; Mfr_name: TEXAS INSTRUMENTS; Mistral Part No: 141214090006-R; Package: NFBGA212; Part_type: ICS\DIGITAL\MICROCONTROLLER; Power Pins Visible: False; Primitive: DEFAULT; Project: GALILEO_EVM; RoHS: RoHS; Temperature: -40°C+85°C; Tolerance: NA; Voltage: NA; Wattage: NA; Weight: NA; Datasheet: Y:\MIS_DATABASE\DATASHEETS\ICS\DIGITAL\MICROCONTROLLER\TM4C129XNCZAD.PDF

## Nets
3V3_CONN_PG: U20.U15(PQ6/EN0RXD1/U1DTR) ; also on sheet 50
3V3_DCIN_PG: U20.W12(PQ5/EN0RXD0/U1TX) ; also on sheet 50
5V_EN: U20.M1(PC5/C1+/EPI0S6/RTCCLK/T7CCP1/U7TX) ; also on sheet 50
5V_PWRGD: U20.B8(PP6/AIN23/I2C2SDA/U1DCD) ; also on sheet 50
DGND: C32.2 C33.1 C34.1 C35.2 C36.2 C37.2 C38.2 C39.2 C40.1 C41.1 C58.1 C396.1 C397.1 C400.2 C403.2 C435.2 C799.2 D6.2(A) D7.2(A) D8.2(A) D9.2(A) D10.2(A) D11.2(A) J6.2 J7.4 J7.8 J7.10 J7.12 J9.3 J10.2 MOD1.11(VSS) MOD1.K Q8.2(S) Q9.2(S) Q10.2(S) Q11.2(S) R40.1 R176.1 R184.1 R191.1 R198.1 R218.2 R226.2 R252.2 R625.1 R652.2 R655.1 R786.2 SW2.3(B1) SW2.4(B2) SW4.3(B1) SW4.4(B2) SW5.3(B1) SW5.4(B2) SW6.3(B1) SW6.4(B2) SW7.3(B1) SW7.4(B2) SW10.3(B1) SW10.4(B2) U13.14(GND) U14.4(GND) U16.4(GND) U21.2(GND) ; also on sheet 1 11 12 13 14 15 16 17 18 19 20 21 22 23 24 25 26 27 28 29 30 31 32 33 34 35 36 37 38 39 40 41 42 43 44 47 48 49 50
GND_OSC: C72.2 C80.2 R652.1 ; also on sheet 47
V0: C35.1 MOD1.1(V0)
V1: C36.1 MOD1.2(V1)
V2: C37.1 MOD1.3(V2)
V3: C38.1 MOD1.4(V3)
V4: C39.1 MOD1.5(V4)
VCC3V0_BMC_BKL: MOD1.A R100.2
VCC3V0_BMC_LCD: R112.1 ; also on sheet 47
VCC3V3_BMC: C58.2 C400.1 C403.1 C435.1 R103.2 R106.1 R132.1 R134.1 R135.1 R168.2 R175.2 R179.2 R180.2 R183.2 R188.2 R190.2 R193.2 R196.2 R197.2 R199.2 R202.2 R204.2 R219.2 R224.2 R225.2 R227.2 R254.2 R264.2 R289.2 R313.2 R591.1 R601.2 R645.1 R646.1 R659.2 R660.2 R661.1 R662.2 R663.1 R664.2 R878.2 U13.15(VCC) U14.8(VCCB) U16.8(VCCB) U21.4(VDD) ; also on sheet 13 28 29 37 38 47 50
VCC3V3_DCIN: C396.2 C397.2 R192.1 R588.1 R589.1 R844.1 R845.1 U14.1(VCCA) U16.1(VCCA) ; also on sheet 11 17 18 19 20 21 22 23 24 25 26 27 28 29 30 31 32 33 34 35 36 37 38 43 44 47 48 50
VCC5V0_DCDC: R592.1 ; also on sheet 21 22 27 30 44 48 49 50
VCC_BMC_LCD: C33.2 C34.2 MOD1.12(VDD) R100.1 R106.2 R112.2
ATTENTIONz: D10.1(K) R289.1 SW7.1(A1) SW7.2(A2) U20.D6(PP0/C2+/EN0INTRN/SSI3XDAT2/T6CCP0/U6RX)
BMC_AUDIO_RSTn: R193.1 U20.K19(PM1/EPI0S14/T2CCP1) ; also on sheet 47
BMC_BLUE_LED: R602.2 U20.K3(PC7/C0-/EPI0S4/U5TX)
BMC_BOOTMODE0: U20.D12(PS0/LCDDATA20/M0FAULT0/T2CCP0) ; also on sheet 38
BMC_BOOTMODE1: U20.R13(PS7/EN0RXDV/LCDDATA09/T5CCP1) ; also on sheet 38
BMC_BOOTMODE2: U20.D13(PS1/LCDDATA21/M0FAULT1/T2CCP1) ; also on sheet 38
BMC_BOOTMODE3: U20.A14(PS3/LCDDATA23/M0FAULT3/T3CCP1) ; also on sheet 38
BMC_BOOTMODE4: U20.T13(PS5/EN0TXD1/LCDDATA07/PHB0/T4CCP1) ; also on sheet 38
BMC_BOOTMODE5: U20.B14(PS2/LCDDATA22/M0FAULT2/T3CCP0/U1DSR) ; also on sheet 38
BMC_BOOTMODE6: U20.U10(PS6/EN0RXER/IDX0/LCDDATA08/T5CCP0) ; also on sheet 38
BMC_BOOTMODE7: U20.P2(PR5/I2C3SDA/LCDDATA01/M0PWM5/T0CCP1/U1RX) ; also on sheet 38
BMC_BOOTMODE8: U20.V9(PS4/EN0TXD0/LCDDATA06/PHA0/T4CCP0) ; also on sheet 38
BMC_BOOTMODE9: U20.N4(PR1/I2C1SDA/LCDFP/M0PWM1/U4RX) ; also on sheet 38
BMC_BOOTMODE10: U20.W9(PR6/I2C4SCL/LCDDATA04/M0PWM6/T1CCP0/U1TX) ; also on sheet 38
BMC_BOOTMODE11: U20.R10(PR7/EN0TXEN/I2C4SDA/LCDDATA05/M0PWM7/T1CCP1) ; also on sheet 38
BMC_BOOTMODE12: U20.N5(PR0/I2C1SCL/LCDCP/M0PWM0/U4TX) ; also on sheet 38
BMC_BOOTMODE13: U20.V8(PR3/I2C2SDA/LCDDATA03/M0PWM3) ; also on sheet 38
BMC_BOOTMODE14: U20.N2(PR2/I2C2SCL/LCDLP/M0PWM2) ; also on sheet 38
BMC_BOOTMODE15: U20.P3(PR4/I2C3SCL/LCDDATA00) ; also on sheet 38
BMC_BOOTSELECT: J10.1 R225.1 U20.V2(PH7/U5TX/U7TX)
BMC_CDCM_RST: U20.E7(PJ1/U3TX) ; also on sheet 47
BMC_CLK_PDN: U20.T8(PF6/LCDMCLK) ; also on sheet 37
BMC_CLK_REF_SEL: U20.F16(PJ3/LCDDATA15/U2CTS) ; also on sheet 47
BMC_CLK_SYNC: U20.U8(PF7/LCDDATA02) ; also on sheet 37
BMC_EEPROM_WP: U20.E17(PJ5/LCDDATA17/U3CTS) ; also on sheet 47
BMC_EMMC_RSTn: R204.1 U20.N18(PM7/EN0COL/T5CCP1/TMPR0/U0RI) ; also on sheet 47
BMC_ETH_RSTn: R199.1 U20.K18(PM0/EPI0S15/T2CCP0) ; also on sheet 47
BMC_FLASH_RESET#: U20.F18(PJ4/LCDDATA16/U3RTS) ; also on sheet 47
BMC_FLASH_WPn: U20.H17(PJ2/LCDDATA14/U2RTS) ; also on sheet 47
BMC_GPIO0: R164.2 ; also on sheet 33
BMC_GPIO1: R162.2 ; also on sheet 33
BMC_GPIO3: R161.2 ; also on sheet 33
BMC_GPIO4: R163.2 ; also on sheet 33
BMC_GPIO5: R160.2 ; also on sheet 33
BMC_GPIO6: R221.2 ; also on sheet 33
BMC_GREEN_LED: R41.2 R601.1 U20.L2(PC6/C0+/EPI0S5/U5RX)
BMC_HDMI_RSTn: R662.1 U20.L18(PM2/EPI0S13/T3CCP0) ; also on sheet 47
BMC_HIBn: TP98.1(TP) U20.M17(~{HIB})
BMC_I2C0_SCL: R844.2 U14.2(SCLA) ; also on sheet 48
BMC_I2C0_SDA: R845.2 U14.3(SDAA) ; also on sheet 48
BMC_I2C1_SCL: R200.1 R661.2 U16.7(SCLB)
BMC_I2C1_SDA: R203.1 R663.2 U16.6(SDAB)
BMC_JTAG_TCK: R639.1 U20.B15(PC0/SWCLK/TCK)
BMC_JTAG_TDI: J7.3 U20.D14(PC2/TDI)
BMC_JTAG_TDO: J7.7 R878.1 U20.C14(PC3/SWO/TDO)
BMC_JTAG_TMS: J7.1 R188.1 U20.C15(PC1/SWDIO/TMS)
BMC_JTAG_TRSTn: J7.2 R786.1 TP176.1(TP)
BMC_LCD_A0: MOD1.15(A0) U20.F1(PB7/I2C6SDA/T6CCP1)
BMC_LCD_RSTn: MOD1.16(~{RST}) U20.F2(PB6/I2C6SCL/T6CCP0)
BMC_LRESETn: U20.C18(PL6/T1CCP0/USB0DP) ; also on sheet 47
BMC_LRESETNMIENn: U20.B18(PL7/T1CCP1/USB0DM) ; also on sheet 47
BMC_MLB_RSTn: R659.1 U20.G15(PM5/T4CCP1/TMPR2/U0DCD) ; also on sheet 47
BMC_NMIn: R180.1 R655.2 U20.G16(PL0/EPI0S16/I2C2SDA/M0FAULT3/USB0D0) ; also on sheet 47
BMC_OSC0: C80.1 R171.2 U20.E19(OSC0) Y3.1(HOT1)
BMC_OSC1: C72.1 R171.1 U20.D19(OSC1) Y3.3(HOT2)
BMC_PCIe_RSTn: R202.1 U20.N19(PM6/EN0CRS/T5CCP0/TMPR1/U0DSR) ; also on sheet 47
BMC_PORn: J16.2 U20.G19(PL5/EPI0S33/T0CCP1/USB0D5) ; also on sheet 47
BMC_QSPI_RSTn: R660.1 U20.L19(PM3/EPI0S12/T3CCP1) ; also on sheet 47
BMC_RESET_FULLn: U20.H19(PL1/EPI0S17/I2C2SCL/PHA0/USB0D1) ; also on sheet 47
BMC_RESETz: C799.1 D9.1(K) R254.1 R885.2 U20.P18(~{RST})
BMC_RSV6_TOGGLE: U20.C8(PJ0/EN0PPS/U3RX) ; also on sheet 47
BMC_SOC_RESETn: U20.H18(PL4/EPI0S26/T0CCP0/USB0D4) ; also on sheet 47
BMC_SPI1_CLK: MOD1.14(SCL) U20.B6(PB5/AIN11/I2C5SDA/SSI1CLK/U0RTS)
BMC_SPI1_CSn: MOD1.17(~{CS1}) U20.C6(PB4/AIN10/I2C5SCL/SSI1FSS/U0CTS)
BMC_SPI1_MOSI: MOD1.13(SI) R170.1 R177.1
BMC_SYSCLKSEL: J15.2 U20.K5(PJ7/U4CTS) ; also on sheet 47
BMC_TSC_WAKEn: R664.1 U20.M18(PM4/EN0RREF_CLK/T4CCP0/TMPR3/U0CTS) ; also on sheet 47
BMC_TXVR_RXD: U13.9(ROUT) ; also on sheet 28
BMC_TXVR_TXD: U13.11(DIN) ; also on sheet 28
BMC_UART0_DETECT: J6.1 R132.2 U20.T2(PH5/EN0PPS/U0RI) ; also on sheet 28
BMC_UART0_EN: R103.1 R625.2 U13.1(~{EN})
BMC_UART0_RX: U20.V3(PA0/CAN0RX/I2C9SCL/T0CCP0/U0RX) ; also on sheet 28
BMC_UART0_TX: U20.W3(PA1/CAN0TX/I2C9SDA/T0CCP1/U0TX) ; also on sheet 28
BMC_UART_SEL: U20.U2(PH6/U5RX/U7RX) ; also on sheet 29
BMC_WAKEn: J9.2 U20.U18(~{WAKE})
BMC_XOSC0: R205.1 U21.3(OUT)
BMC_XOSC0_R: R205.2 U20.T18(XOSC0)
BOOTMODEON: U20.G18(PL2/C0O/EPI0S18/PHB0/USB0D2) ; also on sheet 38
DC_BRD_DET: R192.2 R195.2 ; also on sheet 12 22 33
DIP_SW_B0: R176.2 SW3.1 U20.P4(PH0/EPI0S0/U0RTS)
DIP_SW_B1: R184.2 SW3.2 U20.R2(PH1/EPI0S1/U0CTS)
DIP_SW_B2: R191.2 SW3.3 U20.R1(PH2/EPI0S2/U0DCD)
DIP_SW_B3: R198.2 SW3.4 U20.T1(PH3/EPI0S3/U0DSR)
INT: U20.M3(PQ7/U1RI) ; also on sheet 47
INT1: U20.W10(PT0/CAN0RX/EN0RXD0/LCDDATA10/T6CCP0) ; also on sheet 47
JTAG_PD: J7.5 R179.1
JTAG_RTCK: J7.9 R133.2
nRESPWRON2: U20.A13(PQ4/DIVSCLK/U1RX) ; also on sheet 11 49
PLL_LOCK: U20.R3(PH4/U0DTR) ; also on sheet 36
PMBUS_I2C_EN: U14.5(EN) U20.V16(PK6/EN0LED1/EN0TXD2/EPI0S25/I2C4SCL/M0FAULT1)
PWRON_RSTz: D7.1(K) J9.1 R224.1 SW5.1(A1) SW5.2(A2) U20.D8(PP4/OWIRE/U0DSR/U3RTS/USB0D7)
RS232_RX: J6.4 U13.8(RIN)
RS232_TX: J6.3 U13.13(DOUT)
SOC_ARM_BENDIAN: U20.J18(PL3/C1O/EPI0S19/IDX0/USB0D3) ; also on sheet 38
SOC_ARM_LENDIAN: U20.U19(PK4/EN0INTRN/EN0LED0/EN0RXD3/EPI0S32/I2C3SCL/M0PWM6) ; also on sheet 38
SOC_BOOTCOMPLETE: U20.B13(PP2/EPI0S29/U0DTR/USB0NXT) ; also on sheet 11
SOC_GPIO0_102: U20.H4(PQ2/EPI0S22/SSI3XDAT0/T7CCP0) ; also on sheet 35
SOC_I2C0_SCL: U16.2(SCLA) ; also on sheet 17 26 34 35
SOC_I2C0_SDA: U16.3(SDAA) ; also on sheet 17 26 34 35
SOC_I2C_EN: U16.5(EN) U20.V17(PK5/EN0LED2/EN0RXD2/EPI0S31/I2C3SDA/M0PWM7)
SOC_PLL_LOCK: R39.2 U20.B12(PP5/I2C2SCL/OWALT/U3CTS/USB0D6) ; also on sheet 11
SOC_RESETSTATz: R42.2 U20.C12(PP3/EPI0S30/RTCCLK/U0DCD/U1CTS/USB0DIR) ; also on sheet 11 17 18 21 22 23 25 26 31 33
TRGRSTZ: U20.A8(PP7/AIN22/OWIRE) ; also on sheet 11 43
VOL+: D6.1(K) R168.1 SW2.1(A1) SW2.2(A2) U20.E3(PQ0/EPI0S20/SSI3CLK/T6CCP0)
VOL-: D8.1(K) R196.1 SW4.1(A1) SW4.2(A2) U20.E2(PQ1/EPI0S21/SSI3FSS/T6CCP1)
VPP_EN: U20.W16(PK7/EN0TXD3/EPI0S24/I2C4SDA/M0FAULT2/RTCCLK/U0RI) ; also on sheet 13
WARMRSTz: D11.1(K) R313.1 SW10.1(A1) SW10.2(A2) U20.D7(PP1/C2-/SSI3XDAT3/T6CCP1/U6TX)
N14084176: J7.11 R133.1 R639.2
N14086192: C32.1 MOD1.10(VOUT)
N14096877: R885.1 SW6.1(A1) SW6.2(A2)
N14115400: R154.1 R645.2 U14.6(SDAB)
N14119383: Q9.1(G) R40.2 R602.1
N14119459: LD11.1 Q9.3(D)
N14119466: LD12.1 Q10.3(D)
N14119875: Q10.1(G) R41.1
N14120120: LD12.2 R591.2
N14120305: LD11.2 R592.2
N18024893: R153.1 R646.2 U14.7(SCLB)
N18029281: R170.2 U20.A5(PE4/AIN9/SSI1XDAT0/U1RI)
N18029296: R177.2 U20.B5(PE5/AIN8/SSI1XDAT1)
N18114221: TP182.1(TP) U20.F17(PT3/CAN1TX/LCDDATA19/T7CCP1)
N18887648: C384.2 MOD1.8(C1+)
N18887654: C384.1 MOD1.9(C1-)
N18887823: C385.2 MOD1.7(C2+)
N18887827: C385.1 MOD1.6(C2-)
N19628213: TP73.1(TP) U20.K1(PK2/AIN18/EPI0S2/U4RTS)
N19628231: TP72.1(TP) U20.K2(PK3/AIN19/EPI0S3/U4CTS)
N19748787: TP69.1(TP) U20.C2(PD0/AIN15/C0O/I2C7SCL/SSI2XDAT1/T0CCP0)
N19748789: TP70.1(TP) U20.C1(PD1/AIN14/C1O/I2C7SDA/SSI2XDAT0/T0CCP1)
N19748805: TP71.1(TP) U20.D2(PD2/AIN13/C2O/I2C8SCL/SSI2FSS/T1CCP0)
N19748807: TP81.1(TP) U20.D1(PD3/AIN12/I2C8SDA/SSI2CLK/T1CCP1)
N19748859: TP78.1(TP) U20.B4(PD5/AIN6/SSI1XDAT3/T3CCP1/U2TX)
N19748861: TP79.1(TP) U20.B3(PD6/AIN5/SSI2XDAT3/T4CCP0/U2RTS/USB0EPEN)
N19748877: TP80.1(TP) U20.B2(PD7/AIN4/NMT/SSI2XDAT2/T4CCP1/U2CTS/USB0PFLT)
N19749721: LD10.1 Q8.3(D)
N19749727: Q8.1(G) R39.1
N19749733: LD10.2 R589.2
N19749927: LD13.1 Q11.3(D)
N19749933: Q11.1(G) R42.1
N19749935: LD13.2 R588.2
N19752176: R226.1 U20.W15(RBIAS)
N19752383: R227.1 U21.1(Tri_State)
N19771684: R164.1 U20.A11(PN2/EPI0S29/U1DCD/U2RTS)
N19771691: R162.1 U20.B10(PN3/EPI0S30/U1DSR/U2CTS)
N19771705: R161.1 U20.B9(PN5/EPI0S35/I2C2SCL/U1RI/U3CTS)
N19771712: R163.1 U20.B11(PN1/U1CTS)
N19771719: R160.1 U20.C10(PN0/U1RTS)
N19771726: R221.1 U20.T12(PN6/EN0TXER/LCDDATA13/U4RTS)
N19776797: J15.3 R219.1
N19776809: J15.1 R218.1
N19935623: R200.2 U20.N15(PG0/EN0PPS/EPI0S11/I2C1SCL/M0PWM4)
N19935654: R203.2 U20.T14(PG1/EPI0SI0/I2C1SDA/M0PWM5)
N19936542: TP181.1(TP) U20.M16(PG3/EN0TXEN/I2C2SDA/SSI2XDAT2)
N19936548: TP180.1(TP) U20.V11(PG2/EN0TXCK/I2C2SCL/SSI2XDAT3)
N19998418: TP97.1(TP) U20.T19(XOSC1)
N20088320: TP56.1(TP) U20.A4(PD4/AIN7/SSI1XDAT2/T3CCP0/U2RX)
N20324932: R153.2 U20.A17(PB2/EN0MDC/EPI0S27/I2C0SCL/T5CCP0/USB0STP)
N20324951: R154.2 U20.B17(PB3/EN0MDIO/EPI0S28/I2C0SDA/T5CCP1/USB0CLK)
N20326127: TP86.1(TP) U20.U12(PN7/LCDDATA12/U1RTS/U4CTS)
N20326675: TP58.1(TP) U20.J1(PK0/AIN16/EPI0S0/U4RX)
N20326684: TP59.1(TP) U20.J2(PK1/AIN17/EPI0S1/U4TX)
N20327036: TP75.1(TP) U20.G2(PE3/AIN0/OWIRE/U1DTR)
N20327038: TP74.1(TP) U20.G1(PE2/AIN1/U1DCD)
N20327047: TP76.1(TP) U20.H2(PE1/AIN2/U1DSR)
N20327049: TP77.1(TP) U20.H3(PE0/AIN3/U1RTS)
N20327072: TP66.1(TP) U20.A7(PE6/AIN20/I2C9SCL/U0CTS)
N20327098: TP67.1(TP) U20.B7(PE7/AIN21/I2C9SDA/NMI/U0RTS)
N20333819: TP54.1(TP) U20.A10(PN4/EPI0S34/I2C2SDA/U1DTR/U3RTS)
N20333845: R195.1 U20.M4(PQ3/EPI0S23/SSI3XDAT1/T7CCP1)
N20474037: J16.1 R264.1
N20474249: J16.3 R252.1
N21171769: TP21.1(TP) U20.V7(PF4/EN0LED1/M0FAULT0/SSI3XDAT2/TRD3)
N21171778: TP22.1(TP) U20.W7(PF5/SSI3XDAT3)
N21184349: TP19.1(TP) U20.N1(PJ6/LCDAC/U4RTS)
N21499820: TP13.1(TP) U20.V10(PT1/CAN0TX/EN0RXD1/LCDDATA11/T6CCP1)
N22388793: TP96.1(TP) U20.T7(PF3/EN0MDIO/M0PWM3/SSI3CLK/TRCLK)
N22388802: TP94.1(TP) U20.V6(PF1/EN0LED2/M0PWM1/SSI3XDAT0/TRD1)
N22388818: TP95.1(TP) U20.U6(PF0/EN0LED0/M0PWM0/SSI3XDAT1/TRD2)
N22388827: TP93.1(TP) U20.W6(PF2/EN0MDC/M0PWM2/SSI3FSS/TRD0)
N26188507: TP68.1(TP) U20.M2(PC4/C1-/EPI0S7/T7CCP0/U7RX)
N27263094: C394.1 U13.6(C2-)
N27263096: C394.2 U13.5(C2+)
N27263102: C391.1 U13.2(C1+)
N27263104: C391.2 U13.4(C1-)
N27263131: C41.2 U13.3(V+)
N27263145: C40.2 U13.7(V-)
N27263153: R135.2 U13.16(~{FORCEOFF})
N27263155: R134.2 U13.12(FORCEON)
N29296054: R190.1 SW3.7
N29296055: R175.1 SW3.5
N29296056: R183.1 SW3.6
N29296057: R197.1 SW3.8

Not connected (* = marked no-connect by the designer): J7 6* 13* 14*; U13 10(~{INVALID})*; U20 C5(NC1)* E13(NC2)* E18(PT2/CAN1RX/LCDDATA18/T7CCP0)* V13(EN0RXIN)* V14(EN0TXON)* V15(EN0TXOP)* V18(NC3)* V19(NC4)* W13(EN0RXIP)* W18(NC5)* W19(NC6)*; Y3 2(NC1)* 4(NC2)*

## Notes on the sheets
sheet 45
- BMC JTAG
- BMC I2C1
- I2C ADDRESS:  0x0 (PROGRAMMABLE)
- BMC LCD
- BMC I2C0
- BMC TEST POINTS
- BMC
- BMC UART0
- JUMPER SELECTION FOR SOC SYS CLOCK
  SHOULD BE LOW FOR INTERNAL HF OSCILLATOR
sheet 46
- BMC
- BMC CLOCK
- JUMPER SELECTION BASED ON THE SOC_SYSCLKSEL
- DIP SWITCH
- BMC BOOT SELECT
- PUSH BUTTON
  SWITCHES
- LEDS
- LED BLUE
- LED GREEN
- POWER ON INDICATION
- LED BLUE
- LED GREEN
